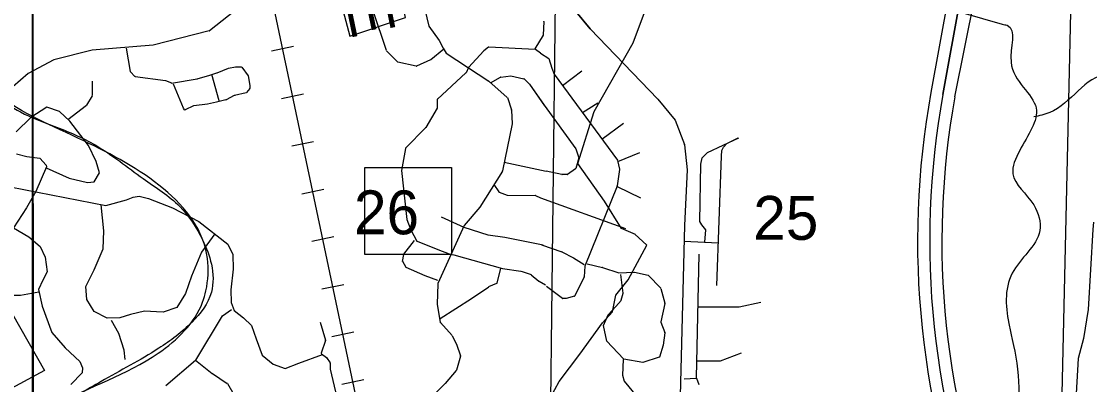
# Model space of a CAD drawing. Extents: x 408847 to 817539, y 923858 to 1151780.
# Drawn here: x 499771 to 510743, y 1052511 to 1056242 of the extents above; entities that cross this region are included whole.
import ezdxf

# ---------------------------------------------------------------- set-up
doc = ezdxf.new("R2010")
doc.units = 0
for name, color, linetype in [('Interstate Divided Highway Outline and Fill', 7, 'Continuous'), ('Level 12', 7, 'Continuous'), ('Level 39', 7, 'Continuous'), ('Level 4', 7, 'Continuous'), ('Level 43', 7, 'Continuous'), ('Local Roads Improved', 7, 'Continuous'), ('Local Roads Paved', 7, 'Continuous'), ('Narrow River Creek and Branch and Slough', 7, 'Continuous'), ('Railroads', 7, 'Continuous'), ('Railroads Text', 7, 'Continuous'), ('Section Lines', 7, 'Continuous'), ('Township  and Range lines', 7, 'Continuous')]:
    doc.layers.add(name, color=color, linetype=linetype)

msp = doc.modelspace()

# ---------------------------------------------------------------- linework, layer by layer
at = {"layer": 'Interstate Divided Highway Outline and Fill'}
for p, q in [((509835, 1059480), (509113, 1055512)), ((509359, 1055467), (510169, 1059502))]:
    msp.add_line(p, q, dxfattribs=at)
for radius in [8525, 8275]:
    msp.add_arc((517500, 1053985), radius, 169.6781, 202.3328, dxfattribs=at)
at = {"layer": 'Level 12'}
msp.add_spline([(495603, 1046713), (495762, 1046773), (495913, 1047052), (495882, 1047477), (496295, 1047971), (496439, 1048510), (496372, 1048947), (496341, 1049046), (496285, 1049225), (496199, 1049510), (496116, 1049787), (497150, 1050216), (497142, 1050322), (497305, 1050639), (497840, 1051013), (498239, 1051585), (498453, 1051721), (499480, 1051938), (500137, 1052304), (501177, 1052834), (501632, 1053358), (501666, 1053474), (501682, 1053807), (500411, 1055014), (499513, 1055498), (499223, 1055797), (499087, 1056246), (499139, 1056468), (499557, 1057135), (500200, 1057900), (500386, 1058050), (500935, 1058091), (501236, 1058391), (501326, 1058954), (501606, 1059771), (501783, 1060031)], degree=3, dxfattribs=at)
at = {"layer": 'Level 39'}
msp.add_lwpolyline([(502348, 1059082), (503143, 1056091), (503715, 1056282), (503015, 1059273)], close=True, dxfattribs=at)
at = {"layer": 'Level 4'}
for p, q in [((509958, 1059458), (509236, 1055490)), ((509236, 1055490), (509958, 1059458))]:
    msp.add_line(p, q, dxfattribs=at)
msp.add_arc((517500, 1053985), 8400, 169.6781, 202.3328, dxfattribs=at)
at = {"layer": 'Level 43'}
for points in [[(503298, 1054740), (504189, 1054740), (504189, 1053849), (503298, 1053849)], [(496414, 1051517), (499681, 1053234), (500010, 1052657), (496780, 1050914)]]:
    msp.add_lwpolyline(points, close=True, dxfattribs=at)
at = {"layer": 'Local Roads Improved'}
for p, q in [((505464, 1056343), (505612, 1056165)), ((505464, 1056343), (505612, 1056165)), ((505612, 1056165), (506307, 1055443)), ((505612, 1056165), (506307, 1055443)), ((504590, 1055610), (504693, 1055669)), ((504695, 1055670), (504798, 1055682)), ((504799, 1055682), (504932, 1055651)), ((504934, 1055650), (504989, 1055596)), ((504989, 1055596), (505143, 1055374)), ((506307, 1055443), (506485, 1055228)), ((506307, 1055443), (506485, 1055228)), ((506485, 1055227), (506583, 1054976)), ((506485, 1055227), (506583, 1054976)), ((506583, 1054975), (506608, 1054717)), ((506583, 1054975), (506608, 1054717)), ((506608, 1054717), (506583, 1054145)), ((506608, 1054717), (506583, 1054145)), ((506583, 1054145), (506528, 1051993)), ((506583, 1054145), (506528, 1051997))]:
    msp.add_line(p, q, dxfattribs=at)
for centre, start, end in [((504695, 1055666), 96.7129, 119.7564), ((504798, 1055678), 77.19, 96.7129), ((504932, 1055648), 44.9867, 77.19), ((504986, 1055593), 34.7653, 44.9867), ((506304, 1055440), 39.6311, 43.8802), ((506304, 1055440), 39.6311, 43.8802), ((506481, 1055225), 21.3089, 39.6311), ((506481, 1055225), 21.3089, 39.6311), ((506579, 1054974), 5.4378, 21.3089), ((506579, 1054974), 5.4378, 21.3089), ((506604, 1054717), 357.5383, 5.4378), ((506604, 1054717), 357.5383, 5.4378), ((506587, 1054145), 177.5383, 178.5277), ((506587, 1054145), 177.5383, 178.5252)]:
    msp.add_arc(centre, 4, start, end, dxfattribs=at)
at = {"layer": 'Local Roads Paved'}
for p, q in [((501963, 1056350), (501702, 1056144)), ((503520, 1055941), (503383, 1056350)), ((503913, 1056365), (503956, 1056193)), ((505612, 1056165), (505464, 1056343)), ((503957, 1056192), (504061, 1056045)), ((505136, 1056241), (505130, 1056101)), ((505612, 1056165), (506307, 1055443)), ((501701, 1056143), (501124, 1055996)), ((505130, 1056099), (505044, 1055959)), ((500497, 1055947), (500104, 1055848)), ((501124, 1055996), (500497, 1055947)), ((500846, 1055965), (500889, 1055726)), ((500846, 1055965), (500889, 1055726)), ((503636, 1055824), (503521, 1055940)), ((504109, 1055956), (503975, 1055848)), ((504061, 1056045), (504104, 1055965)), ((504104, 1055965), (504134, 1055916)), ((504522, 1055940), (504362, 1055769)), ((504570, 1055976), (504522, 1055940)), ((505049, 1055953), (504572, 1055977)), ((505103, 1055915), (505051, 1055952)), ((500103, 1055848), (499840, 1055707)), ((503974, 1055848), (503828, 1055781)), ((504135, 1055915), (504571, 1055627)), ((505103, 1055915), (505187, 1055862)), ((505188, 1055859), (505219, 1055762)), ((500890, 1055724), (500937, 1055677)), ((500890, 1055724), (500937, 1055677)), ((501781, 1055713), (501897, 1055762)), ((501781, 1055713), (501897, 1055762)), ((501898, 1055762), (501971, 1055774)), ((501898, 1055762), (501971, 1055774)), ((501971, 1055774), (502030, 1055774)), ((501971, 1055774), (502030, 1055774)), ((502034, 1055773), (502099, 1055683)), ((502034, 1055773), (502099, 1055683)), ((503826, 1055781), (503638, 1055823)), ((504362, 1055767), (504338, 1055713)), ((505219, 1055762), (505243, 1055701)), ((505330, 1055583), (505526, 1055732)), ((499839, 1055707), (499502, 1055412)), ((500503, 1055481), (500503, 1055627)), ((500940, 1055676), (501251, 1055633)), ((500940, 1055676), (501251, 1055633)), ((501252, 1055633), (501312, 1055609)), ((501252, 1055633), (501312, 1055609)), ((501314, 1055608), (501577, 1055651)), ((501314, 1055608), (501577, 1055651)), ((501578, 1055651), (501707, 1055688)), ((501578, 1055651), (501707, 1055688)), ((501707, 1055688), (501780, 1055713)), ((501707, 1055688), (501780, 1055713)), ((501725, 1055700), (501799, 1055430)), ((502100, 1055681), (502118, 1055584)), ((502100, 1055681), (502118, 1055584)), ((504337, 1055712), (504044, 1055443)), ((504571, 1055626), (504761, 1055461)), ((504590, 1055610), (504693, 1055669)), ((504695, 1055670), (504798, 1055682)), ((504799, 1055682), (504932, 1055651)), ((504934, 1055650), (504989, 1055596)), ((505244, 1055700), (505894, 1054816)), ((501436, 1055350), (501332, 1055596)), ((501436, 1055350), (501332, 1055596)), ((502080, 1055509), (501959, 1055479)), ((502080, 1055509), (501959, 1055479)), ((502118, 1055552), (502082, 1055511)), ((502118, 1055552), (502082, 1055511)), ((502118, 1055583), (502118, 1055554)), ((502118, 1055583), (502118, 1055554)), ((504989, 1055596), (505139, 1055381)), ((500442, 1055382), (500503, 1055478)), ((501682, 1055393), (501541, 1055375)), ((501682, 1055393), (501541, 1055375)), ((501774, 1055411), (501682, 1055393)), ((501774, 1055411), (501682, 1055393)), ((501872, 1055436), (501774, 1055411)), ((501872, 1055436), (501774, 1055411)), ((501958, 1055479), (501873, 1055436)), ((501958, 1055479), (501873, 1055436)), ((504042, 1055440), (504042, 1055351)), ((504762, 1055460), (504804, 1055332)), ((505533, 1055307), (505692, 1055406)), ((506307, 1055443), (506485, 1055228)), ((500249, 1055234), (500441, 1055381)), ((501447, 1055334), (501436, 1055350)), ((501447, 1055334), (501436, 1055350)), ((501540, 1055374), (501452, 1055333)), ((501540, 1055374), (501452, 1055333)), ((504042, 1055349), (503926, 1055153)), ((504805, 1055331), (504811, 1055190)), ((505139, 1055381), (505464, 1054933)), ((504811, 1055189), (504712, 1054705)), ((505734, 1055033), (505956, 1055197)), ((506485, 1055227), (506583, 1054976)), ((503925, 1055153), (503717, 1054939)), ((506583, 1054975), (506608, 1054717)), ((503716, 1054937), (503674, 1054711)), ((505465, 1054932), (505495, 1054841)), ((505897, 1054803), (506122, 1054895)), ((504731, 1054794), (505161, 1054704)), ((505495, 1054839), (505465, 1054731)), ((505895, 1054814), (505913, 1054724)), ((503674, 1054710), (503729, 1054207)), ((504712, 1054704), (504479, 1054335)), ((505323, 1054668), (505161, 1054704)), ((505377, 1054668), (505324, 1054668)), ((505463, 1054728), (505380, 1054669)), ((505913, 1054722), (505889, 1054551)), ((506608, 1054717), (506583, 1054145)), ((504624, 1054565), (504675, 1054490)), ((505889, 1054550), (505557, 1053728)), ((505889, 1054545), (506128, 1054428)), ((504677, 1054489), (504761, 1054458)), ((504762, 1054458), (505050, 1054452)), ((505051, 1054452), (505102, 1054428)), ((505102, 1054428), (505975, 1054114)), ((504479, 1054335), (504319, 1054145)), ((503729, 1054206), (503772, 1054102)), ((504319, 1054126), (504085, 1054231)), ((503772, 1054101), (503833, 1053986)), ((504319, 1054144), (504049, 1053549)), ((504564, 1054046), (504319, 1054126)), ((506583, 1054145), (506528, 1051997)), ((503699, 1053850), (503809, 1053991)), ((503835, 1053984), (504048, 1053899)), ((504737, 1054022), (504565, 1054046)), ((505130, 1053942), (504737, 1054022)), ((506579, 1053985), (506929, 1053967)), ((504049, 1053899), (504165, 1053856)), ((504165, 1053856), (504214, 1053843)), ((505114, 1053948), (505323, 1053875)), ((505323, 1053874), (505440, 1053813)), ((503686, 1053777), (503698, 1053848)), ((503722, 1053715), (503687, 1053774)), ((504214, 1053843), (504712, 1053702)), ((505440, 1053813), (505551, 1053745)), ((505581, 1053752), (505741, 1053715)), ((506706, 1052581), (506731, 1053850)), ((503919, 1053628), (503724, 1053714)), ((504657, 1053556), (504694, 1053702)), ((504713, 1053702), (504902, 1053677)), ((504903, 1053677), (505007, 1053641)), ((505008, 1053640), (505087, 1053573)), ((505557, 1053726), (505551, 1053617)), ((505741, 1053715), (505906, 1053660)), ((505908, 1053659), (506066, 1053665)), ((505950, 1053451), (505926, 1053641)), ((506067, 1053665), (506207, 1053635)), ((506209, 1053634), (506337, 1053500)), ((504048, 1053579), (503919, 1053628)), ((504048, 1053547), (504042, 1053339)), ((504571, 1053518), (504655, 1053553)), ((505088, 1053573), (505155, 1053536)), ((505550, 1053615), (505453, 1053421)), ((504393, 1053394), (504571, 1053517)), ((505328, 1053396), (505163, 1053518)), ((505451, 1053419), (505367, 1053395)), ((505932, 1053377), (505950, 1053449)), ((506338, 1053498), (506380, 1053347)), ((504042, 1053339), (504073, 1053150)), ((504073, 1053191), (504393, 1053394)), ((505366, 1053395), (505331, 1053395)), ((505797, 1053229), (505876, 1053315)), ((505876, 1053315), (505931, 1053376)), ((506380, 1053345), (506338, 1053156)), ((506720, 1053309), (507142, 1053309)), ((507143, 1053309), (507364, 1053358)), ((501561, 1052762), (501837, 1053216)), ((501838, 1053217), (501929, 1053284)), ((505748, 1053119), (505796, 1053228)), ((500694, 1053174), (500767, 1053039)), ((502838, 1053151), (502893, 1052968)), ((504074, 1053148), (504196, 1053014)), ((505784, 1052959), (505748, 1053117)), ((506338, 1053154), (506380, 1053045)), ((500768, 1053038), (500823, 1052867)), ((504196, 1053013), (504239, 1052928)), ((506380, 1053043), (506362, 1052915)), ((500823, 1052866), (500835, 1052768)), ((502893, 1052965), (502851, 1052834)), ((504239, 1052928), (504282, 1052807)), ((505955, 1052775), (505785, 1052957)), ((506362, 1052915), (506326, 1052794)), ((501253, 1052503), (501560, 1052761)), ((501560, 1052761), (501732, 1052626)), ((502852, 1052829), (502905, 1052789)), ((502906, 1052788), (502941, 1052734)), ((504282, 1052804), (504239, 1052659)), ((505950, 1052768), (505944, 1052608)), ((506152, 1052737), (505958, 1052774)), ((506323, 1052792), (506154, 1052737)), ((506953, 1052756), (507167, 1052836)), ((502942, 1052732), (502942, 1052672)), ((502942, 1052671), (503126, 1051879)), ((504238, 1052657), (504122, 1052523)), ((506712, 1052756), (506951, 1052756)), ((501733, 1052626), (501885, 1052522)), ((505944, 1052607), (505962, 1052547)), ((505963, 1052546), (506090, 1052394)), ((506577, 1052571), (506702, 1052577)), ((506706, 1052577), (506730, 1052511)), ((501887, 1052521), (501953, 1052411)), ((504122, 1052522), (504024, 1052424))]:
    msp.add_line(p, q, dxfattribs=at)
for points in [[(500027, 1054737), (500263, 1054633), (500450, 1054587), (500517, 1054594), (500574, 1054685), (500540, 1054804), (500459, 1054966), (500267, 1055217), (500164, 1055316), (500033, 1055360), (499869, 1055256), (499719, 1055106)], [(506789, 1053974), (506800, 1054102), (506758, 1054153), (506738, 1054188), (506751, 1054774), (506762, 1054839), (506817, 1054894), (507141, 1055046)], [(506913, 1053529), (506961, 1054857), (506965, 1054915), (506982, 1054950), (507017, 1054988), (507134, 1055046)], [(499722, 1054881), (499826, 1054854), (499959, 1054836), (500025, 1054764), (500029, 1054747), (499919, 1054494), (499825, 1054327), (499689, 1054121), (499848, 1054029), (499965, 1053931), (500016, 1053820), (500037, 1053671), (499990, 1053585), (499945, 1053487), (499986, 1053316), (500084, 1053045), (500222, 1052889), (500370, 1052747), (500398, 1052682), (500396, 1052632), (500279, 1052511)], [(499231, 1054626), (500638, 1054350), (500852, 1054408), (500919, 1054436), (500982, 1054445), (501075, 1054423), (501322, 1054326), (501595, 1054188), (501890, 1053952), (501941, 1053849), (501945, 1053697), (501923, 1053483), (501925, 1053356), (501956, 1053272), (502053, 1053197), (502135, 1053117), (502183, 1052981), (502243, 1052813), (502357, 1052720), (502481, 1052676), (502619, 1052730), (502865, 1052820)], [(501758, 1054058), (501622, 1053871), (501519, 1053626), (501458, 1053446), (501368, 1053304), (501228, 1053254), (501159, 1053257), (501034, 1053267), (500892, 1053231), (500781, 1053196), (500651, 1053193), (500517, 1053262), (500444, 1053384), (500433, 1053518), (500517, 1053691), (500611, 1053905), (500616, 1054090), (500592, 1054359)], [(499951, 1053460), (499762, 1053427), (499623, 1053425), (499511, 1053510), (499480, 1053638), (499461, 1053799), (499457, 1053928), (499466, 1054005), (499488, 1054080), (499530, 1054121), (499696, 1054131)], [(510782, 1054179), (510777, 1054105), (510726, 1053281), (510680, 1052984), (510624, 1052780), (510588, 1052120)]]:
    msp.add_lwpolyline(points, dxfattribs=at)
for centre, start, end in [((503960, 1056194), 194.03, 215.2986), ((505132, 1056242), 357.5116, 0.7772), ((501700, 1056147), 284.3291, 308.2424), ((505126, 1056101), 328.6832, 357.5116), ((500498, 1055943), 94.4867, 104.0425), ((501123, 1056000), 274.4867, 284.3291), ((503523, 1055942), 198.4873, 224.9867), ((504057, 1056043), 28.2896, 35.2986), ((504107, 1055967), 208.2896, 211.9934), ((504524, 1055937), 126.8827, 137.1344), ((504572, 1055973), 87.063, 126.8827), ((505049, 1055949), 54.9217, 87.063), ((500105, 1055845), 104.0425, 118.1527), ((503973, 1055851), 294.6337, 308.6728), ((504137, 1055918), 211.9934, 236.4843), ((505185, 1055858), 17.3464, 57.201), ((500893, 1055727), 190.1709, 224.9867), ((500893, 1055727), 190.1709, 224.9867), ((501898, 1055758), 99.4667, 112.8432), ((501898, 1055758), 99.4667, 112.8432), ((501971, 1055770), 90, 99.4667), ((501971, 1055770), 90, 99.4667), ((502030, 1055770), 36.2411, 90), ((502030, 1055770), 36.2411, 90), ((503639, 1055827), 224.9867, 257.2699), ((503827, 1055785), 257.2699, 294.6337), ((504365, 1055766), 137.1344, 156.0474), ((505223, 1055764), 197.3464, 201.7922), ((499842, 1055704), 118.1527, 131.1253), ((500940, 1055680), 224.9867, 262.1811), ((500940, 1055680), 224.9867, 262.1811), ((501251, 1055629), 68.1894, 82.1811), ((501251, 1055629), 68.1894, 82.1811), ((501314, 1055612), 248.1894, 279.2503), ((501314, 1055612), 248.1894, 279.2503), ((501577, 1055655), 279.2503, 285.9524), ((501577, 1055655), 279.2503, 285.9524), ((501705, 1055692), 285.9524, 288.443), ((501705, 1055692), 285.9524, 288.443), ((501779, 1055716), 288.443, 292.8432), ((501779, 1055716), 288.443, 292.8432), ((502096, 1055680), 10.6148, 36.2411), ((502096, 1055680), 10.6148, 36.2411), ((504334, 1055715), 312.5237, 336.0474), ((504568, 1055623), 48.932, 56.4843), ((504695, 1055666), 96.7129, 119.7564), ((504798, 1055678), 77.19, 96.7129), ((504932, 1055648), 44.9867, 77.19), ((505247, 1055703), 201.7922, 216.3445), ((502079, 1055513), 284.0425, 319.4119), ((502079, 1055513), 284.0425, 319.4119), ((502114, 1055583), 0, 10.6148), ((502114, 1055583), 0, 10.6148), ((502114, 1055554), 319.4119, 0), ((502114, 1055554), 319.4119, 0), ((504986, 1055593), 34.9253, 44.9867), ((500499, 1055481), 328.0066, 0), ((501681, 1055397), 277.4348, 281.3151), ((501681, 1055397), 277.4348, 281.3151), ((501773, 1055415), 281.3151, 284.0425), ((501773, 1055415), 281.3151, 284.0425), ((501871, 1055440), 284.0425, 296.5757), ((501871, 1055440), 284.0425, 296.5757), ((501960, 1055475), 104.0425, 116.5757), ((501960, 1055475), 104.0425, 116.5757), ((504046, 1055440), 132.5237, 180), ((504758, 1055458), 18.4269, 48.932), ((506304, 1055440), 39.6311, 43.8802), ((500439, 1055384), 307.1976, 328.0066), ((501440, 1055352), 203.0159, 213.6777), ((501440, 1055352), 203.0159, 213.6777), ((501450, 1055336), 213.6777, 295.0271), ((501450, 1055336), 213.6777, 295.0271), ((501542, 1055371), 97.4348, 115.0271), ((501542, 1055371), 97.4348, 115.0271), ((504038, 1055351), 329.312, 0), ((504801, 1055331), 2.4884, 18.4269), ((504807, 1055190), 348.5559, 2.4884), ((506481, 1055225), 21.3089, 39.6311), ((503922, 1055156), 315.8437, 329.312), ((506579, 1054974), 5.4378, 21.3089), ((503720, 1054936), 135.8437, 169.2918), ((505461, 1054930), 18.4269, 35.968), ((505491, 1054840), 344.4828, 18.4269), ((505461, 1054732), 305.5503, 344.4828), ((505891, 1054814), 11.3048, 36.3445), ((503678, 1054710), 169.2918, 186.2606), ((504709, 1054706), 327.6646, 348.5559), ((505324, 1054672), 257.3501, 270), ((505377, 1054672), 270, 305.5503), ((505909, 1054723), 351.8736, 11.3048), ((506604, 1054717), 357.5383, 5.4378), ((505885, 1054552), 338.0606, 351.8736), ((504678, 1054492), 213.6777, 250.3377), ((504762, 1054462), 250.3377, 268.7806), ((505049, 1054448), 64.9533, 88.7806), ((504475, 1054338), 320.0263, 327.6646), ((503733, 1054207), 186.2606, 202.3707), ((503776, 1054103), 202.3707, 207.7475), ((504322, 1054142), 140.0263, 155.6106), ((504320, 1054130), 245.8878, 251.988), ((506587, 1054145), 177.5383, 178.5252), ((503836, 1053988), 207.7475, 248.1894), ((504566, 1054050), 251.988, 261.8662), ((504736, 1054018), 78.5128, 81.8662), ((504050, 1053902), 248.1894, 249.7665), ((504166, 1053859), 249.7665, 255.9575), ((505322, 1053871), 62.2305, 70.5516), ((503690, 1053776), 170.542, 210.952), ((503702, 1053848), 141.9659, 170.542), ((504213, 1053839), 74.1411, 75.9575), ((505438, 1053810), 58.5586, 62.2305), ((503725, 1053717), 210.952, 246.3608), ((504713, 1053706), 254.1411, 262.6442), ((504902, 1053673), 70.5516, 82.6442), ((505005, 1053637), 49.7505, 70.5516), ((505561, 1053726), 158.0606, 176.8216), ((505740, 1053711), 71.557, 76.9995), ((505908, 1053663), 251.557, 272.2036), ((506067, 1053661), 77.7297, 92.2036), ((506206, 1053631), 43.6544, 77.7297), ((503921, 1053632), 246.3608, 249.1367), ((504052, 1053547), 155.6106, 178.3161), ((504654, 1053557), 293.2083, 345.97), ((505090, 1053576), 229.7505, 241.3783), ((505547, 1053617), 333.4456, 356.8216), ((504573, 1053514), 113.2083, 124.6048), ((505450, 1053423), 285.9524, 333.4456), ((505946, 1053450), 345.97, 7.349), ((506334, 1053497), 15.6353, 43.6544), ((504046, 1053339), 178.3161, 189.1582), ((504390, 1053398), 302.4119, 304.6048), ((505331, 1053399), 233.4584, 270), ((505366, 1053399), 270, 285.9524), ((505873, 1053318), 317.1344, 318.0261), ((505928, 1053378), 318.0261, 345.97), ((506376, 1053346), 347.2814, 15.6353), ((507142, 1053313), 270, 282.5345), ((501840, 1053214), 126.2666, 148.7077), ((505800, 1053227), 137.1344, 156.0474), ((504077, 1053150), 189.1582, 222.2604), ((505752, 1053118), 156.0474, 192.9888), ((506342, 1053155), 167.2814, 201.2415), ((500764, 1053037), 17.8111, 28.5992), ((504193, 1053011), 26.9188, 42.2604), ((506376, 1053044), 351.8736, 21.2415), ((500819, 1052865), 7.1217, 17.8111), ((502889, 1052967), 342.3576, 16.6919), ((505788, 1052960), 192.9888, 223.0117), ((506358, 1052916), 343.3081, 351.8736), ((501557, 1052764), 310.0434, 328.7077), ((502855, 1052833), 162.3576, 232.1121), ((502902, 1052785), 33.6777, 52.1121), ((504278, 1052805), 343.747, 19.2817), ((505958, 1052777), 223.0117, 259.3755), ((506322, 1052795), 287.8267, 343.3081), ((506951, 1052760), 270, 290.3852), ((502938, 1052732), 360, 33.6777), ((502946, 1052672), 180, 193.086), ((504235, 1052660), 319.1981, 343.747), ((506153, 1052741), 259.3755, 287.8267), ((501735, 1052629), 231.8298, 235.7719), ((505948, 1052608), 177.7984, 196.6919), ((505966, 1052548), 196.6919, 220.0171), ((506702, 1052581), 272.7276, 358.8935), ((501883, 1052519), 31.4177, 55.7719), ((504119, 1052525), 315.0133, 319.1981)]:
    msp.add_arc(centre, 4, start, end, dxfattribs=at)
at = {"layer": 'Narrow River Creek and Branch and Slough'}
for points in [[(499858, 1060490), (499863, 1060250), (499993, 1060174), (500297, 1059777), (500304, 1059146), (499883, 1058485), (499880, 1051164), (499529, 1046002), (499522, 1044940)], [(506080, 1054052), (505936, 1054114), (505760, 1054395), (505487, 1054782), (505655, 1055317), (506053, 1056020), (506418, 1056995), (505771, 1059350), (505403, 1059905)], [(509016, 1057964), (508858, 1056500), (509844, 1056212)], [(507653, 1050074), (507450, 1051496), (505207, 1052380), (505296, 1052543), (505508, 1052823), (505739, 1053147), (505843, 1053257), (505877, 1053429), (506004, 1053587), (506196, 1053944), (506070, 1054056)]]:
    msp.add_lwpolyline(points, dxfattribs=at)
for points in [[(501824, 1060609), (501722, 1059930), (501578, 1059571), (501416, 1059193), (501290, 1058798), (501254, 1058528), (501146, 1058277), (500823, 1058097), (500499, 1058097), (500320, 1058007), (500014, 1057773), (499619, 1057306), (499457, 1056910), (499187, 1056551), (499079, 1056227), (499115, 1055958), (499223, 1055724), (499493, 1055490), (499762, 1055311), (500104, 1055167), (500535, 1054969), (501021, 1054628), (501398, 1054340), (501632, 1053999), (501722, 1053747), (501722, 1053459), (501524, 1053154), (501182, 1052884), (500589, 1052543), (500158, 1052291), (499673, 1052039), (499259, 1051878), (498864, 1051824), (498486, 1051698), (498199, 1051518), (497983, 1051249), (497749, 1050979), (497462, 1050763), (497264, 1050583), (497156, 1050350), (497102, 1050116), (496851, 1050026), (496649, 1049988)], [(514188, 1059608), (513409, 1059719), (512993, 1059453), (512678, 1059440), (512340, 1059386), (512120, 1059262), (512133, 1058677), (512337, 1058150), (512019, 1057169), (511642, 1056346), (511349, 1055671), (510926, 1055701), (510333, 1055305), (510170, 1055261)], [(509844, 1056212), (509894, 1056201), (509935, 1055824), (510193, 1055352), (510025, 1054917), (509954, 1054677), (510168, 1054356), (510230, 1054093), (509947, 1053655), (509918, 1053106), (509948, 1052974), (509937, 1051998), (509793, 1051762), (509648, 1051641)]]:
    msp.add_spline(points, degree=3, dxfattribs=at)
at = {"layer": 'Railroads'}
for p, q in [((502341, 1055940), (502566, 1055988)), ((502444, 1055451), (502669, 1055498)), ((502547, 1054962), (502772, 1055009)), ((502651, 1054472), (502876, 1054520)), ((502754, 1053983), (502979, 1054031)), ((502857, 1053494), (503082, 1053541)), ((502960, 1053005), (503185, 1053052)), ((503063, 1052515), (503288, 1052563))]:
    msp.add_line(p, q, dxfattribs=at)
for points in [[(510079, 1019797), (501500, 1060485), (501513, 1060426), (495656, 1088706), (495656, 1088706), (495297, 1089286), (494680, 1089503), (494680, 1089503), (486589, 1089534), (486589, 1089534), (485948, 1089769), (485608, 1090360), (485593, 1090535), (485593, 1090535), (485599, 1095822), (485578, 1096141), (484280, 1105896), (484265, 1106104), (484317, 1113718)], [(511050, 1014994), (510079, 1019797), (501500, 1060485)]]:
    msp.add_lwpolyline(points, dxfattribs=at)
at = {"layer": 'Section Lines'}
msp.add_line((499890, 1056754), (499892, 1051445), dxfattribs=at)
msp.add_lwpolyline([(505255, 1056749), (505196, 1051461)], dxfattribs=at)
at = {"layer": 'Township  and Range lines'}
msp.add_line((510558, 1056792), (510435, 1051473), dxfattribs=at)

# ---------------------------------------------------------------- texts
at = {"layer": 'Level 43'}
for s, p in [('26', (503186, 1054056)), ('25', (507287, 1053999))]:
    msp.add_text(s, height=450, rotation=359.9062, dxfattribs=at).set_placement(p)
at = {"layer": 'Railroads Text'}
msp.add_text('SEMINOLE', height=450, rotation=281.7846, dxfattribs=at).set_placement((502543, 1059099))

doc.saveas('drawing.dxf')
